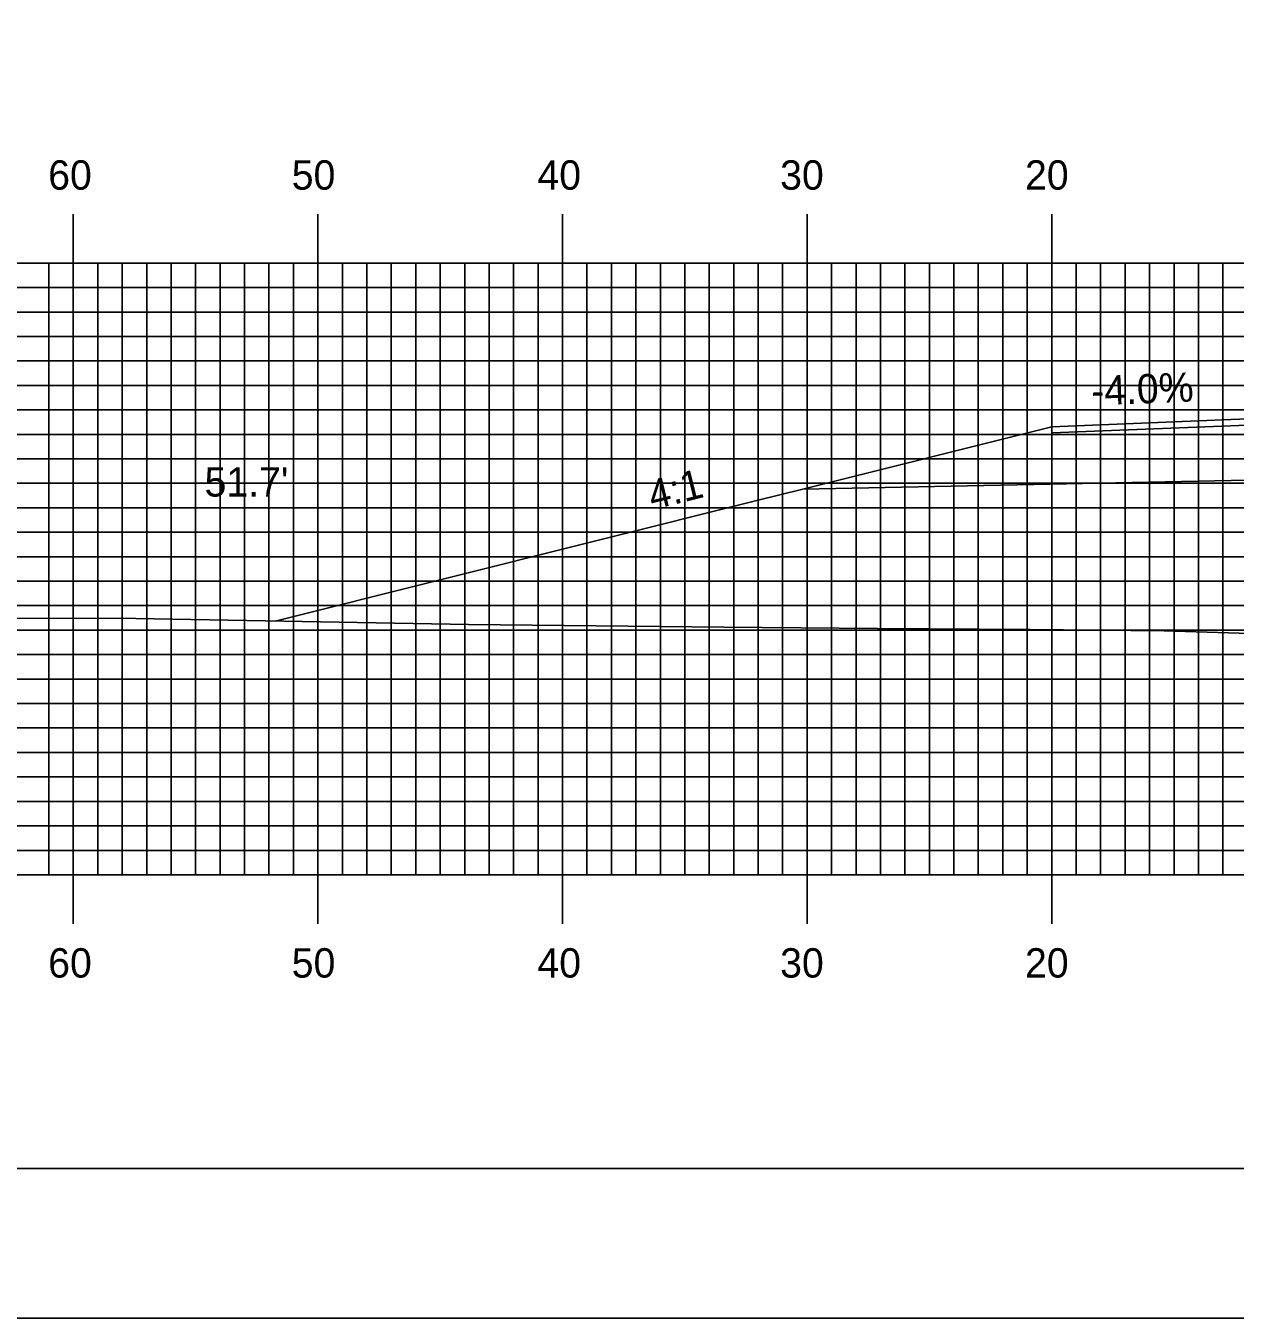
# Model space of a CAD drawing. Extents: x 1804290 to 1804634, y 442591 to 442811.
# Drawn here: x 1804394.2 to 1804443.7, y 442590.5 to 442643.4 of the extents above; entities that cross this region are included whole.
import ezdxf

# ---------------------------------------------------------------- set-up
doc = ezdxf.new("R2010")
doc.units = 0
for name, color, linetype in [('ANNOTATION', 7, 'Continuous'), ('BORDER', 7, 'Continuous'), ('D_Roadway_Centerline', 7, 'Continuous'), ('D_Roadway_Edge_Shoulder', 7, 'Continuous'), ('D_Roadway_SlopeLines', 7, 'Continuous'), ('D_Roadway_SubGrade', 7, 'Continuous'), ('D_Text_Standard', 7, 'Continuous'), ('H_V ANNOTATION', 7, 'Continuous'), ('MAJOR', 7, 'Continuous'), ('MINOR', 7, 'Continuous'), ('PLOT BOUNDARY', 7, 'Continuous'), ('S_Roadway_Centerline', 7, 'Continuous')]:
    doc.layers.add(name, color=color, linetype=linetype)

msp = doc.modelspace()

# ---------------------------------------------------------------- linework, layer by layer
at = {"layer": 'BORDER'}
msp.add_lwpolyline([(1804306.567, 442596.665), (1804626.567, 442596.665), (1804626.567, 442806.665), (1804306.567, 442806.665)], close=True, dxfattribs=at)
at = {"layer": 'D_Roadway_Centerline'}
msp.add_lwpolyline([(1804404.418, 442619.036), (1804424.167, 442623.973), (1804425.993, 442624.43), (1804436.167, 442626.973), (1804444.167, 442627.293), (1804456.167, 442627.581), (1804468.167, 442627.869), (1804476.167, 442627.549), (1804486.341, 442625.006), (1804488.167, 442624.549), (1804509.679, 442617.379)], dxfattribs=at)
at = {"layer": 'D_Roadway_Edge_Shoulder'}
msp.add_lwpolyline([(1804444.167, 442627.293), (1804436.167, 442626.973), (1804436.167, 442626.723), (1804444.167, 442627.043)], close=True, dxfattribs=at)
at = {"layer": 'D_Roadway_SlopeLines'}
msp.add_lwpolyline([(1804436.167, 442626.973), (1804425.993, 442624.43), (1804424.167, 442623.973), (1804404.418, 442619.036)], dxfattribs=at)
at = {"layer": 'D_Roadway_SubGrade'}
msp.add_lwpolyline([(1804444.167, 442624.793), (1804425.993, 442624.43), (1804436.167, 442626.973), (1804436.167, 442626.723), (1804444.167, 442627.043), (1804456.167, 442627.331), (1804468.167, 442627.619), (1804476.167, 442627.299), (1804476.167, 442627.549), (1804486.341, 442625.006), (1804468.167, 442625.369), (1804456.167, 442625.081)], close=True, dxfattribs=at)
at = {"layer": 'MAJOR'}
for p, q in [((1804396.167, 442635.669), (1804396.167, 442633.665)), ((1804406.167, 442635.669), (1804406.167, 442633.665)), ((1804416.167, 442635.669), (1804416.167, 442633.665)), ((1804426.167, 442635.669), (1804426.167, 442633.665)), ((1804436.167, 442635.669), (1804436.167, 442633.665)), ((1804316.167, 442633.665), (1804596.167, 442633.665)), ((1804316.167, 442633.665), (1804596.167, 442633.665)), ((1804396.167, 442608.665), (1804396.167, 442633.665)), ((1804406.167, 442608.665), (1804406.167, 442633.665)), ((1804416.167, 442608.665), (1804416.167, 442633.665)), ((1804426.167, 442608.665), (1804426.167, 442633.665)), ((1804436.167, 442608.665), (1804436.167, 442633.665)), ((1804316.167, 442628.665), (1804596.167, 442628.665)), ((1804316.167, 442623.665), (1804596.167, 442623.665)), ((1804316.167, 442618.665), (1804596.167, 442618.665)), ((1804316.167, 442613.665), (1804596.167, 442613.665)), ((1804316.167, 442608.665), (1804596.167, 442608.665)), ((1804316.167, 442608.665), (1804596.167, 442608.665)), ((1804396.167, 442606.661), (1804396.167, 442608.665)), ((1804406.167, 442606.661), (1804406.167, 442608.665)), ((1804416.167, 442606.661), (1804416.167, 442608.665)), ((1804426.167, 442606.661), (1804426.167, 442608.665)), ((1804436.167, 442606.661), (1804436.167, 442608.665))]:
    msp.add_line(p, q, dxfattribs=at)
at = {"layer": 'MINOR'}
for p, q in [((1804395.167, 442608.665), (1804395.167, 442633.665)), ((1804397.167, 442608.665), (1804397.167, 442633.665)), ((1804398.167, 442608.665), (1804398.167, 442633.665)), ((1804399.167, 442608.665), (1804399.167, 442633.665)), ((1804400.167, 442608.665), (1804400.167, 442633.665)), ((1804401.167, 442608.665), (1804401.167, 442633.665)), ((1804402.167, 442608.665), (1804402.167, 442633.665)), ((1804403.167, 442608.665), (1804403.167, 442633.665)), ((1804404.167, 442608.665), (1804404.167, 442633.665)), ((1804405.167, 442608.665), (1804405.167, 442633.665)), ((1804407.167, 442608.665), (1804407.167, 442633.665)), ((1804408.167, 442608.665), (1804408.167, 442633.665)), ((1804409.167, 442608.665), (1804409.167, 442633.665)), ((1804410.167, 442608.665), (1804410.167, 442633.665)), ((1804411.167, 442608.665), (1804411.167, 442633.665)), ((1804412.167, 442608.665), (1804412.167, 442633.665)), ((1804413.167, 442608.665), (1804413.167, 442633.665)), ((1804414.167, 442608.665), (1804414.167, 442633.665)), ((1804415.167, 442608.665), (1804415.167, 442633.665)), ((1804417.167, 442608.665), (1804417.167, 442633.665)), ((1804418.167, 442608.665), (1804418.167, 442633.665)), ((1804419.167, 442608.665), (1804419.167, 442633.665)), ((1804420.167, 442608.665), (1804420.167, 442633.665)), ((1804421.167, 442608.665), (1804421.167, 442633.665)), ((1804422.167, 442608.665), (1804422.167, 442633.665)), ((1804423.167, 442608.665), (1804423.167, 442633.665)), ((1804424.167, 442608.665), (1804424.167, 442633.665)), ((1804425.167, 442608.665), (1804425.167, 442633.665)), ((1804427.167, 442608.665), (1804427.167, 442633.665)), ((1804428.167, 442608.665), (1804428.167, 442633.665)), ((1804429.167, 442608.665), (1804429.167, 442633.665)), ((1804430.167, 442608.665), (1804430.167, 442633.665)), ((1804431.167, 442608.665), (1804431.167, 442633.665)), ((1804432.167, 442608.665), (1804432.167, 442633.665)), ((1804433.167, 442608.665), (1804433.167, 442633.665)), ((1804434.167, 442608.665), (1804434.167, 442633.665)), ((1804435.167, 442608.665), (1804435.167, 442633.665)), ((1804437.167, 442608.665), (1804437.167, 442633.665)), ((1804438.167, 442608.665), (1804438.167, 442633.665)), ((1804439.167, 442608.665), (1804439.167, 442633.665)), ((1804440.167, 442608.665), (1804440.167, 442633.665)), ((1804441.167, 442608.665), (1804441.167, 442633.665)), ((1804442.167, 442608.665), (1804442.167, 442633.665)), ((1804443.167, 442608.665), (1804443.167, 442633.665)), ((1804316.167, 442632.665), (1804596.167, 442632.665)), ((1804316.167, 442631.665), (1804596.167, 442631.665)), ((1804316.167, 442630.665), (1804596.167, 442630.665)), ((1804316.167, 442629.665), (1804596.167, 442629.665)), ((1804316.167, 442627.665), (1804596.167, 442627.665)), ((1804316.167, 442626.665), (1804596.167, 442626.665)), ((1804316.167, 442625.665), (1804596.167, 442625.665)), ((1804316.167, 442624.665), (1804596.167, 442624.665)), ((1804316.167, 442622.665), (1804596.167, 442622.665)), ((1804316.167, 442621.665), (1804596.167, 442621.665)), ((1804316.167, 442620.665), (1804596.167, 442620.665)), ((1804316.167, 442619.665), (1804596.167, 442619.665)), ((1804316.167, 442617.665), (1804596.167, 442617.665)), ((1804316.167, 442616.665), (1804596.167, 442616.665)), ((1804316.167, 442615.665), (1804596.167, 442615.665)), ((1804316.167, 442614.665), (1804596.167, 442614.665)), ((1804316.167, 442612.665), (1804596.167, 442612.665)), ((1804316.167, 442611.665), (1804596.167, 442611.665)), ((1804316.167, 442610.665), (1804596.167, 442610.665)), ((1804316.167, 442609.665), (1804596.167, 442609.665))]:
    msp.add_line(p, q, dxfattribs=at)
at = {"layer": 'PLOT BOUNDARY'}
msp.add_lwpolyline([(1804290.38, 442590.547), (1804630.38, 442590.547), (1804630.38, 442810.547), (1804290.38, 442810.547)], close=True, dxfattribs=at)
at = {"layer": 'S_Roadway_Centerline'}
msp.add_lwpolyline([(1804390.513, 442619.152), (1804398.724, 442619.134), (1804412.328, 442618.9), (1804422.769, 442618.779), (1804429.045, 442618.732), (1804435.282, 442618.686), (1804440.76, 442618.631), (1804446.9, 442618.439), (1804452.617, 442618.203), (1804457.783, 442618.086), (1804463.95, 442617.925), (1804470.482, 442617.857), (1804475.877, 442617.843), (1804480.82, 442617.828), (1804487.148, 442617.75), (1804495.025, 442617.573), (1804498.588, 442617.507), (1804501.641, 442617.442), (1804509.972, 442617.377), (1804524.543, 442617.769)], dxfattribs=at)

# ---------------------------------------------------------------- texts
at = {"layer": 'ANNOTATION'}
for s, rotation, p in [('-4.0%', 2.2906, (1804437.799, 442627.84)), ('4:1', 14.0362, (1804419.842, 442623.571))]:
    msp.add_text(s, height=1.2, rotation=rotation, dxfattribs=at).set_placement(p)
at = {"layer": 'D_Text_Standard'}
msp.add_text("51.7'", height=1.2, dxfattribs=at).set_placement((1804401.532, 442624.123))
at = {"layer": 'H_V ANNOTATION'}
for s, p in [('60', (1804395.139, 442636.665)), ('50', (1804405.096, 442636.665)), ('40', (1804415.139, 442636.665)), ('30', (1804425.064, 442636.665)), ('20', (1804435.075, 442636.665)), ('60', (1804395.139, 442604.465)), ('50', (1804405.096, 442604.465)), ('40', (1804415.139, 442604.465)), ('30', (1804425.064, 442604.465)), ('20', (1804435.075, 442604.465))]:
    msp.add_text(s, height=1.2, dxfattribs=at).set_placement(p)

doc.saveas('drawing.dxf')
